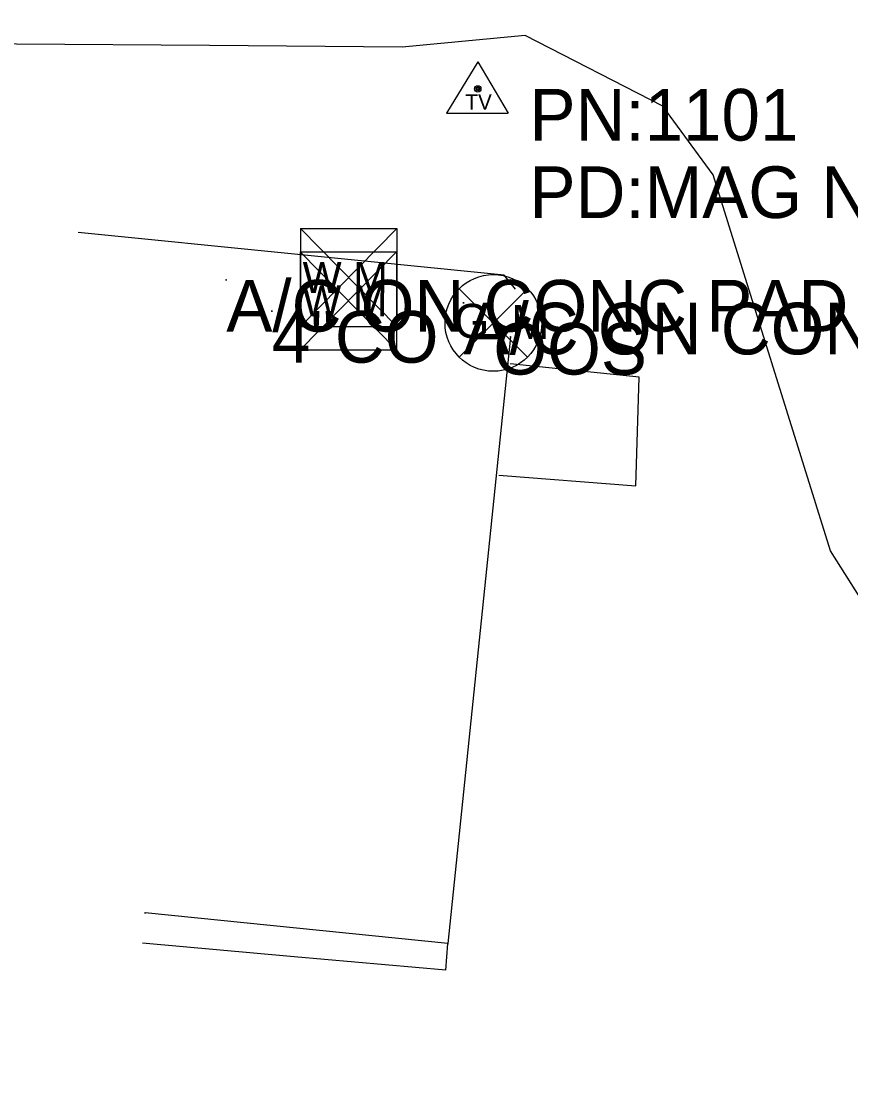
# Model space of a CAD drawing. Extents: x 997398 to 1003416, y 334596 to 337085.
# Drawn here: x 999162 to 999242.3, y 335795.7 to 335899.8 of the extents above; entities that cross this region are included whole.
import ezdxf

# ---------------------------------------------------------------- set-up
doc = ezdxf.new("R2010")
doc.units = 0
for name, color, linetype in [('S_BUILDING', 7, 'Continuous'), ('S_CURB', 7, 'Continuous'), ('S_EDGE_CONCRETE', 7, 'Continuous'), ('S_GAS_UTILITIES', 7, 'Continuous'), ('S_GAS_UTILITIES_ANNOT', 7, 'Continuous'), ('S_MISC_STRUCTURES_ANNOT', 7, 'Continuous'), ('S_MSC_PT_SYM', 7, 'Continuous'), ('S_SANITARY_SEWER_ANNOT', 7, 'Continuous'), ('S_SECONDARY_CTL', 7, 'Continuous'), ('S_SECONDARY_CTL_ANNOT', 7, 'Continuous'), ('S_STR_PT_SYM', 7, 'Continuous'), ('S_UTL_PT_SYM', 7, 'Continuous'), ('S_WATER_UTILITIES', 7, 'Continuous')]:
    doc.layers.add(name, color=color, linetype=linetype)

msp = doc.modelspace()

# ---------------------------------------------------------------- linework, layer by layer
at = {"layer": 'S_BUILDING'}
for p, q in [((999209.36, 335869.22), (999203.3, 335810.51)), ((999203.3, 335810.51), (999174.01, 335813.46))]:
    msp.add_line(p, q, dxfattribs=at)
at = {"layer": 'S_CURB'}
for points in [[(999228.98, 335884.91), (999224.1, 335891.55), (999210.78, 335898.41), (999198.87, 335897.27), (999180.22, 335897.42), (999161.56, 335897.57), (999136.81, 335899.76)], [(999240.32, 335848.52), (999234.65, 335866.71), (999228.98, 335884.91)], [(999309.27, 335795.7), (999307.46, 335796.33), (999284.06, 335804.54), (999270.5, 335812.71), (999253.53, 335827.61), (999240.32, 335848.52)]]:
    msp.add_lwpolyline(points, dxfattribs=at)
at = {"layer": 'S_EDGE_CONCRETE'}
for points in [[(999209.83, 335873.84), (999208.74, 335875.21), (999188.14, 335877.27), (999167.54, 335879.32)], [(999208.23, 335855.85), (999221.47, 335854.81), (999221.81, 335865.32), (999209.32, 335866.63)], [(999203.11, 335807.91), (999188.43, 335809.23), (999173.74, 335810.55)], [(999203.11, 335807.91), (999203.3, 335810.51)]]:
    msp.add_lwpolyline(points, dxfattribs=at)
at = {"layer": 'S_GAS_UTILITIES'}
for p, q in [((999204.39, 335867.27), (999211.01, 335873.89)), ((999204.39, 335873.89), (999211.01, 335867.27))]:
    msp.add_line(p, q, dxfattribs=at)
msp.add_circle((999207.7, 335870.58), 4.68, dxfattribs=at)
at = {"layer": 'S_MSC_PT_SYM'}
for points in [[(999181.86, 335874.74), (999181.86, 335874.79), (999181.86, 335874.74), (999181.81, 335874.74), (999181.86, 335874.74), (999181.86, 335874.69), (999181.86, 335874.74), (999181.91, 335874.74)], [(999204.81, 335872.53), (999204.81, 335872.58), (999204.81, 335872.53), (999204.76, 335872.53), (999204.81, 335872.53), (999204.81, 335872.48), (999204.81, 335872.53), (999204.86, 335872.53)]]:
    msp.add_lwpolyline(points, dxfattribs=at)
at = {"layer": 'S_SECONDARY_CTL'}
for p, q in [((999206.19, 335895.85), (999203.18, 335890.89)), ((999206.19, 335895.85), (999209.14, 335890.89)), ((999203.18, 335890.89), (999209.14, 335890.89))]:
    msp.add_line(p, q, dxfattribs=at)
for radius in [0.311, 0.183, 0.103]:
    msp.add_circle((999206.19, 335893.23), radius, dxfattribs=at)
at = {"layer": 'S_STR_PT_SYM'}
for points in [[(999209.36, 335869.22), (999209.36, 335869.27), (999209.36, 335869.22), (999209.31, 335869.22), (999209.36, 335869.22), (999209.36, 335869.17), (999209.36, 335869.22), (999209.41, 335869.22)], [(999174.01, 335813.46), (999174.01, 335813.51), (999174.01, 335813.46), (999173.96, 335813.46), (999174.01, 335813.46), (999174.01, 335813.41), (999174.01, 335813.46), (999174.06, 335813.46)], [(999203.3, 335810.51), (999203.3, 335810.56), (999203.3, 335810.51), (999203.25, 335810.51), (999203.3, 335810.51), (999203.3, 335810.46), (999203.3, 335810.51), (999203.35, 335810.51)]]:
    msp.add_lwpolyline(points, dxfattribs=at)
at = {"layer": 'S_UTL_PT_SYM'}
msp.add_lwpolyline([(999186.27, 335871.73), (999186.27, 335871.78), (999186.27, 335871.73), (999186.22, 335871.73), (999186.27, 335871.73), (999186.27, 335871.68), (999186.27, 335871.73), (999186.32, 335871.73)], dxfattribs=at)
at = {"layer": 'S_WATER_UTILITIES'}
for p, q in [((999189.03, 335879.72), (999198.37, 335879.72)), ((999189.03, 335879.72), (999189.03, 335870.23)), ((999189.03, 335879.72), (999198.37, 335870.23)), ((999198.37, 335879.72), (999189.03, 335870.23)), ((999198.37, 335879.72), (999198.37, 335870.23)), ((999189, 335877.45), (999198.34, 335877.45)), ((999189, 335877.45), (999189, 335867.96)), ((999189, 335877.45), (999198.34, 335867.96)), ((999198.34, 335877.45), (999189, 335867.96)), ((999198.34, 335877.45), (999198.34, 335867.96)), ((999189.03, 335870.23), (999198.37, 335870.23)), ((999189, 335867.96), (999198.34, 335867.96))]:
    msp.add_line(p, q, dxfattribs=at)

# ---------------------------------------------------------------- texts
at = {"layer": 'S_GAS_UTILITIES'}
for s, p in [('G', (999203.88, 335869.12)), ('M', (999209.44, 335869.01))]:
    msp.add_text(s, height=3.3, rotation=360, dxfattribs=at).set_placement(p)
at = {"layer": 'S_GAS_UTILITIES_ANNOT'}
msp.add_text('OOS', height=5, dxfattribs=at).set_placement((999207.7, 335865.58))
at = {"layer": 'S_MISC_STRUCTURES_ANNOT'}
for p in [(999181.86, 335869.74), (999204.81, 335867.53)]:
    msp.add_text('A/C ON CONC PAD', height=5, dxfattribs=at).set_placement(p)
at = {"layer": 'S_SANITARY_SEWER_ANNOT'}
msp.add_text('4"CO', height=5, dxfattribs=at).set_placement((999186.27, 335866.73))
at = {"layer": 'S_SECONDARY_CTL'}
msp.add_text('TV', height=1.5, rotation=360, dxfattribs=at).set_placement((999204.99, 335891.22))
at = {"layer": 'S_SECONDARY_CTL_ANNOT'}
for s, p in [('PN:1101', (999211.19, 335888.23)), ('PD:MAG NAIL IN ASPH', (999211.19, 335880.73))]:
    msp.add_text(s, height=5, dxfattribs=at).set_placement(p)
at = {"layer": 'S_WATER_UTILITIES'}
for p in [(999189.24, 335873.49), (999189.2, 335871.22)]:
    msp.add_text('W M', height=3, rotation=360, dxfattribs=at).set_placement(p)

doc.saveas('drawing.dxf')
